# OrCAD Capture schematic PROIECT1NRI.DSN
size A
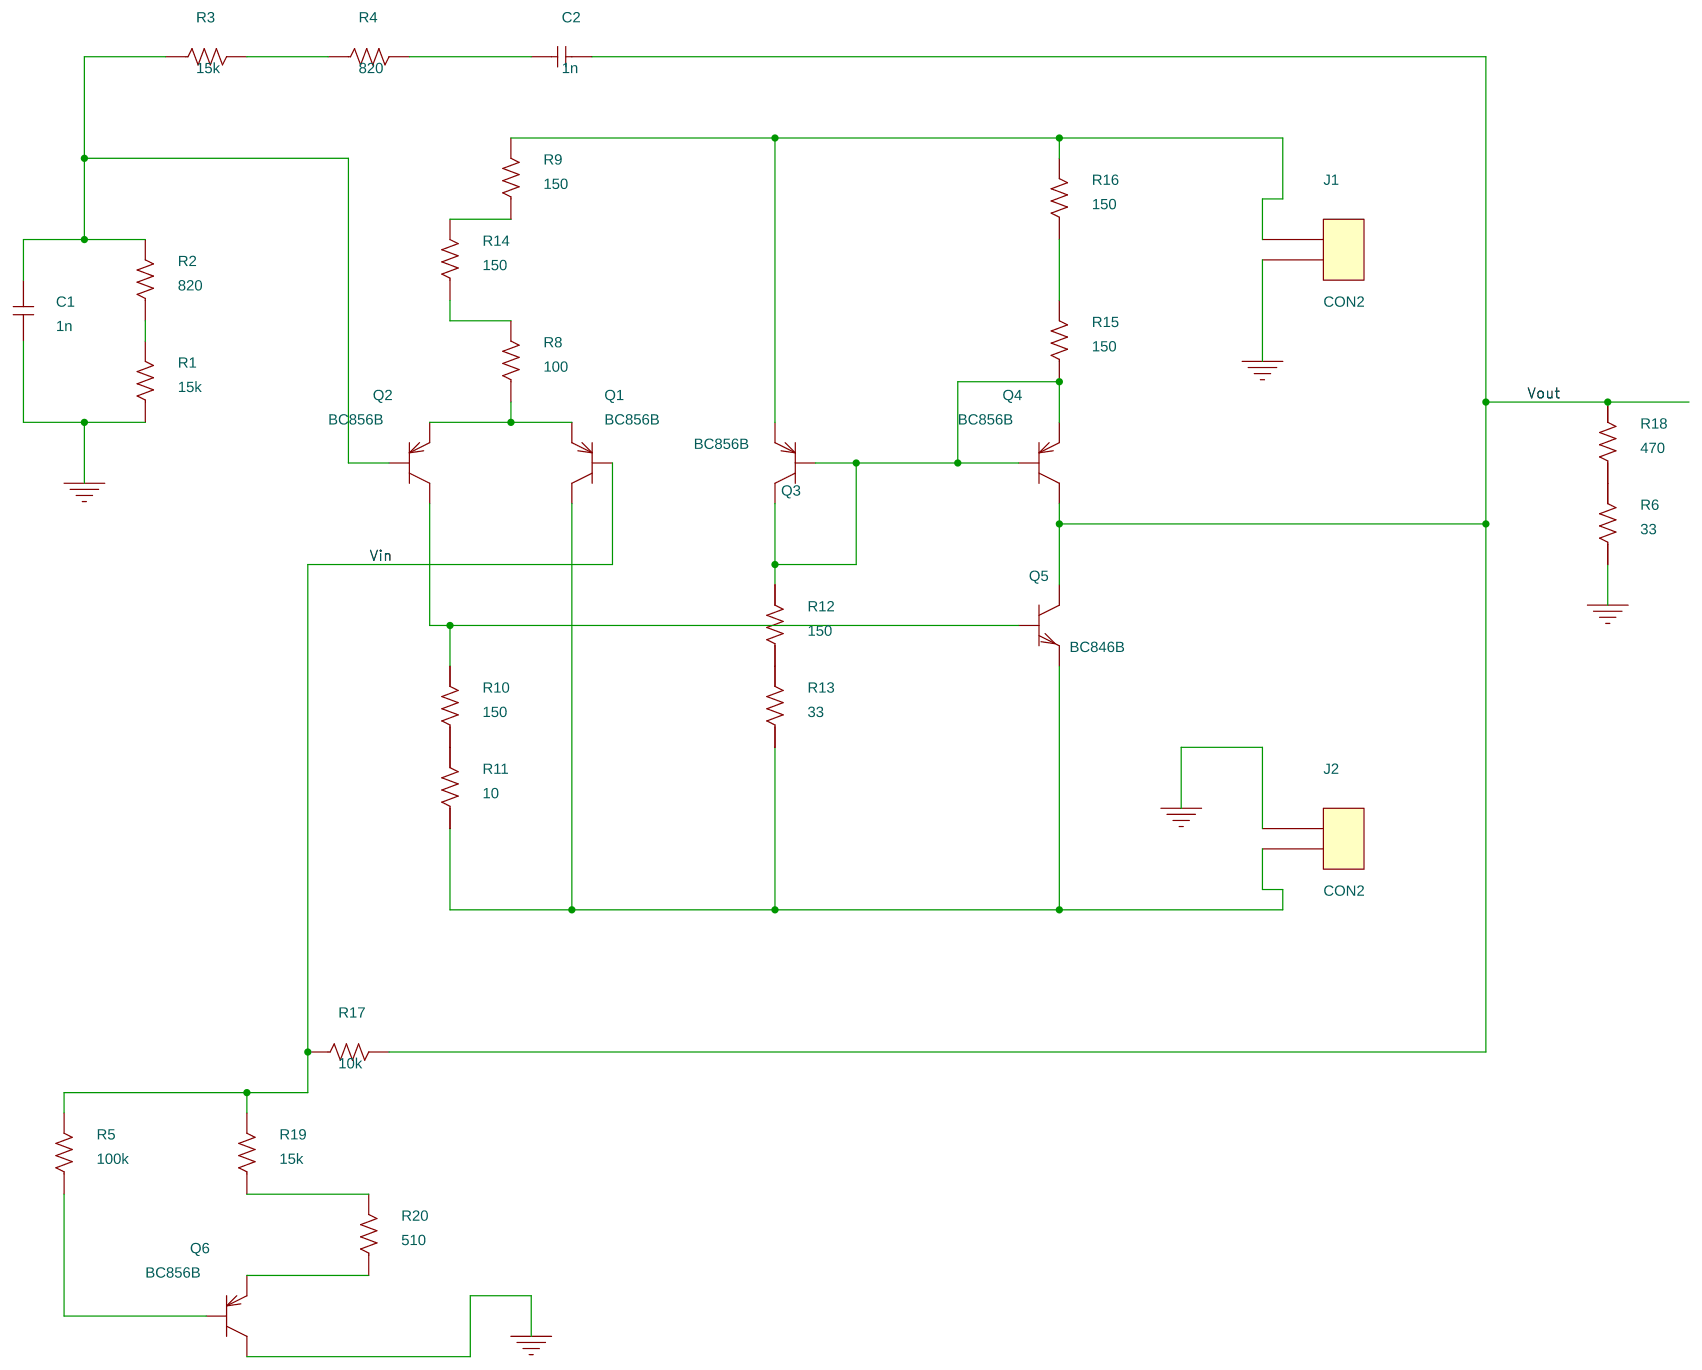
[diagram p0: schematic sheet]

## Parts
C1  1n  [SMC0805]
C2  1n  [SMC0805]
J1  CON2  [SMR2512]
J2  CON2  [SMR2512]
Q1  BC856B  [TO236AA]
Q2  BC856B  [TO236AA]
Q3  BC856B  [TO236AA]
Q4  BC856B  [TO236AA]
Q5  BC846B  [TO236AA]
Q6  BC856B  [TO236AA]
R1  15k  [SMR0805]
R2  820  [SMR0805]
R3  15k  [SMR0805]
R4  820  [SMR0805]
R5  100k  [SMR0805]
R6  33  [SMR0805]
R8  100  [SMR0805]
R9  150  [SMR0805]
R10  150  [SMR0805]
R11  10  [SMR0805]
R12  150  [SMR0805]
R13  33  [SMR0805]
R14  150  [SMR0805]
R15  150  [SMR0805]
R16  150  [SMR0805]
R17  10k  [SMR0805]
R18  470  [SMR0805]
R19  15k  [SMR0805]
R20  510  [SMR0805]

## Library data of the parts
C1 C2 = C
J1 J2 = CON2
Q1-Q4 Q6 = BC856B
Q5 = BC846B
R1-R6 R8-R20 = R

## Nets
GND: C1.1 J1.2 J2.1 Q6.3(c) R1.1 R6.1
Vin: Q1.1(b) R5.2 R17.1 R19.2
Vout: C2.2 Q4.3(c) Q5.3(c) R17.2 R18.2
N10981: C1.2 Q2.1(b) R2.2 R3.1
N10989: R3.2 R4.1
N10993: C2.1 R4.2
N11005: J1.1 Q3.2(e) R9.2 R16.2
N11081: R9.1 R14.2
N11129: R15.2 R16.1
N11169: R8.2 R14.1
N11173: R1.2 R2.1
N11237: Q3.1(b) Q3.3(c) Q4.1(b) Q4.2(e) R12.2 R15.1
N11249: Q1.2(e) Q2.2(e) R8.1
N11403: Q2.3(c) Q5.1(b) R10.2
N11407: J2.2 Q1.3(c) Q5.2(e) R11.1 R13.1
N11711: Q6.1(b) R5.1
N11715: R19.1 R20.2
N11753: Q6.2(e) R20.1
N11884: R10.1 R11.2
N11885: R12.1 R13.2
N11886: R6.2 R18.1
